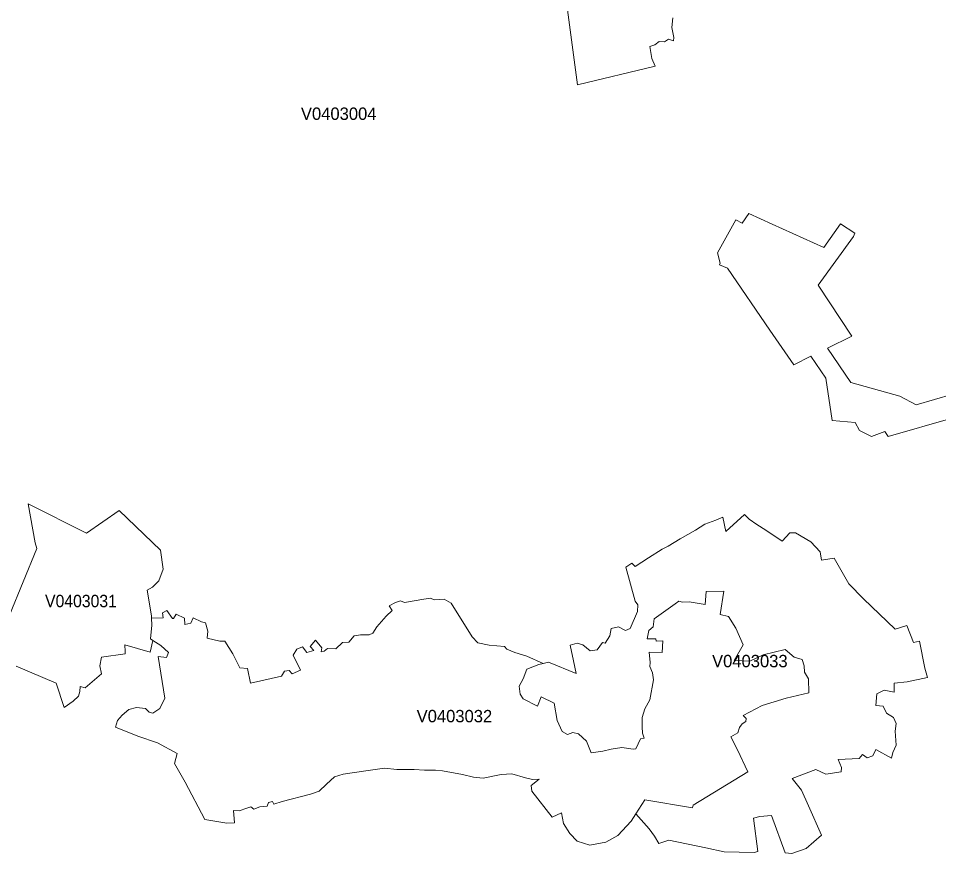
# Model space of a CAD drawing. Extents: x 369010 to 735936, y 6377141 to 6616555.
# Drawn here: x 413706 to 421131, y 6483708 to 6490450 of the extents above; entities that cross this region are included whole.
import ezdxf
from ezdxf.enums import TextEntityAlignment as Align

# ---------------------------------------------------------------- set-up
doc = ezdxf.new("R2010")
doc.units = 0
doc.header["$LTSCALE"] = 40
doc.layers.add('3', color=7, linetype='Continuous', lineweight=13)
doc.layers.add('4', color=7, linetype='Continuous')

msp = doc.modelspace()

# ---------------------------------------------------------------- linework, layer by layer
at = {"layer": '3'}
for points in [[(418988.28, 6490453.3), (418979.01, 6490376.01), (418996.05, 6490295.74), (418992.74, 6490269.76), (418951.04, 6490281.51), (418919.92, 6490261.32), (418877.55, 6490262.64), (418842.96, 6490235.83), (418800.76, 6490223.41), (418818.3, 6490126.1), (418844.62, 6490065.19), (418216.7, 6489912.43), (418137.42, 6490518.34)], [(418137.42, 6490518.34), (418216.7, 6489912.43), (418844.62, 6490065.19), (418818.3, 6490126.1), (418800.76, 6490223.41), (418842.96, 6490235.83), (418877.55, 6490262.64), (418919.92, 6490261.32), (418951.04, 6490281.51), (418992.74, 6490269.76), (418996.05, 6490295.74), (418979.01, 6490376.01), (418988.28, 6490453.3)], [(421250.22, 6487224.48), (420724.08, 6487074.87), (420696.61, 6487116.24), (420590.35, 6487074.7), (420493.54, 6487123.69), (420458.12, 6487186.58), (420273.58, 6487204.29), (420220.45, 6487545.39), (420100.3, 6487722.65), (419962.27, 6487652.48), (419770.94, 6487932.67), (419429.18, 6488432.99), (419362.65, 6488461.29), (419368.6, 6488473.04), (419347.75, 6488558.61), (419494.39, 6488822.59), (419547.18, 6488796.44), (419599.48, 6488874.06), (419787.83, 6488789.82), (420205.56, 6488600.15), (420339.62, 6488792.3), (420455.63, 6488716.5), (420445.87, 6488690.35), (420159.71, 6488296.45), (420430.81, 6487885.01), (420235.51, 6487788.69), (420423.53, 6487511.8), (420819.08, 6487401.08), (420950, 6487331.4), (421393.55, 6487459.33)], [(421393.55, 6487459.33), (420950, 6487331.4), (420819.08, 6487401.08), (420423.53, 6487511.8), (420235.51, 6487788.69), (420430.81, 6487885.01), (420159.71, 6488296.45), (420445.87, 6488690.35), (420455.63, 6488716.5), (420339.62, 6488792.3), (420205.56, 6488600.15), (419787.83, 6488789.82), (419599.48, 6488874.06), (419547.18, 6488796.44), (419494.39, 6488822.59), (419347.75, 6488558.61), (419368.6, 6488473.04), (419362.65, 6488461.29), (419429.18, 6488432.99), (419770.94, 6487932.67), (419962.27, 6487652.48), (420100.3, 6487722.65), (420220.45, 6487545.39), (420273.58, 6487204.29), (420458.12, 6487186.58), (420493.54, 6487123.69), (420590.35, 6487074.7), (420696.61, 6487116.24), (420724.08, 6487074.87), (421250.22, 6487224.48)], [(413522.51, 6485362.56), (413854.84, 6486170.06), (413841.93, 6486217.56), (413784.33, 6486530.36), (414256.35, 6486294.85), (414518.51, 6486477.56), (414851.83, 6486157.15), (414873.68, 6486004.88), (414840.42, 6485910.22), (414789.44, 6485857.42), (414744.09, 6485834.08), (414779.18, 6485628.03), (414779.84, 6485608.67), (414873.35, 6485610.65), (414868.88, 6485652.36), (414903.47, 6485670.57), (414948.65, 6485605.36), (414958.42, 6485605.36), (414980.6, 6485639.28), (415045.81, 6485607.01), (415049.12, 6485556.7), (415097.44, 6485568.45), (415116.31, 6485611.48)], [(413688.34, 6485220.56), (414009.92, 6485083.85), (414076.45, 6484886.08), (414147.95, 6484937.22), (414192.3, 6484977.6), (414202.23, 6485015.67), (414204.05, 6485056.21), (414246.09, 6485047.11), (414377.5, 6485159.16), (414363.93, 6485224.53), (414376.01, 6485292.72), (414568, 6485321.52), (414568.16, 6485338.4), (414564.85, 6485393.84), (414770.24, 6485333.1), (414790.27, 6485428.76), (414772.06, 6485440.35), (414781.83, 6485552.4), (414779.84, 6485608.67), (414779.18, 6485628.03), (414744.09, 6485834.08), (414789.44, 6485857.42), (414840.42, 6485910.22), (414873.68, 6486004.88), (414851.83, 6486157.15), (414518.51, 6486477.56), (414256.35, 6486294.85), (413784.33, 6486530.36), (413841.93, 6486217.56), (413854.84, 6486170.06), (413522.51, 6485362.56)], [(417939.81, 6485242.57), (417983.17, 6485253.16), (418207.59, 6485160.32), (418184.26, 6485262.93), (418159.43, 6485389.54), (418216.2, 6485407.74), (418259.73, 6485394.34), (418320.47, 6485345.52), (418376.57, 6485351.64), (418418.28, 6485412.38), (418441.78, 6485407.08), (418478.03, 6485465.01), (418489.78, 6485524.26), (418548.37, 6485538.66), (418605.8, 6485508.7), (418643.03, 6485525.58), (418701.46, 6485663.45), (418704.11, 6485716.24), (418683.25, 6485745.04), (418608.61, 6486019.61), (418656.28, 6486053.54), (418681.93, 6486025.07), (418789.34, 6486094.92), (418901.39, 6486165.09), (418948.39, 6486188.43), (419046.37, 6486248.84), (419169.34, 6486318.18), (419244.97, 6486367.67), (419333.19, 6486398.95), (419389.79, 6486423.77), (419413.29, 6486307.59), (419564.73, 6486444.46), (419602.46, 6486406.4), (419663.86, 6486363.86), (419738.01, 6486319.34), (419869.75, 6486230.3), (419930.66, 6486295.84), (419975.51, 6486297), (420099.97, 6486223.85), (420176.59, 6486143.41), (420185.53, 6486077.71), (420288.31, 6486091.61), (420406.48, 6485885.55), (420526.47, 6485763.41), (420780.68, 6485520.62), (420874.36, 6485548.75), (420928.81, 6485412.38), (420977.3, 6485421.48), (421019.84, 6485204.34), (421041.68, 6485128.21), (420877.17, 6485093.95), (420773.07, 6485083.19), (420773.73, 6485011.36), (420692.8, 6485026.92), (420633.05, 6484996.8), (420624.45, 6484903.45), (420684.03, 6484899.32), (420710.18, 6484840.56), (420766.45, 6484807.79), (420789.29, 6484758.8), (420781.51, 6484694.92), (420789.29, 6484583.53), (420762.64, 6484522.96), (420750.89, 6484479.1), (420624.78, 6484547.29), (420600.45, 6484496.31), (420556.1, 6484480.09), (420518.2, 6484508.73), (420490.72, 6484476.78), (420322.24, 6484467.02), (420347.06, 6484403.63), (420345.08, 6484369.04), (420221.61, 6484349.02), (420142, 6484385.59), (419950.19, 6484315.25), (420024.66, 6484220.58), (420082.59, 6484092.15), (420187.35, 6483855.81), (420063.72, 6483749.39), (419947.7, 6483707.85), (419892.92, 6483714.47), (419782.86, 6484016.19), (419689.19, 6484008.57), (419638.71, 6483994.84), (419671.64, 6483725.89), (419643.51, 6483716.13), (419401.21, 6483720.93), (419253.74, 6483753.2), (418953.85, 6483816.59), (418874.74, 6483789.12), (418839.32, 6483848.2), (418795.46, 6483909.11), (418688.71, 6484028.6), (418650.98, 6483970.51), (418544.39, 6483854.49), (418445.42, 6483801.36), (418316.83, 6483776.04), (418213.88, 6483807.49), (418155.63, 6483870.54), (418105.81, 6483949.82)], [(420347.06, 6484403.63), (420322.24, 6484467.02), (420490.72, 6484476.78), (420518.2, 6484508.73), (420556.1, 6484480.09), (420600.45, 6484496.31), (420624.78, 6484547.29), (420750.89, 6484479.1), (420762.64, 6484522.96), (420789.29, 6484583.53), (420781.51, 6484694.92), (420789.29, 6484758.8), (420766.45, 6484807.79), (420710.18, 6484840.56), (420684.03, 6484899.32), (420624.45, 6484903.45), (420633.05, 6484996.8), (420692.8, 6485026.92), (420773.73, 6485011.36), (420773.07, 6485083.19), (420877.17, 6485093.95), (421041.68, 6485128.21), (421019.84, 6485204.34), (420977.3, 6485421.48), (420928.81, 6485412.38), (420874.36, 6485548.75), (420780.68, 6485520.62), (420526.47, 6485763.41), (420406.48, 6485885.55), (420288.31, 6486091.61), (420185.53, 6486077.71), (420176.59, 6486143.41), (420099.97, 6486223.85), (419975.51, 6486297), (419930.66, 6486295.84), (419869.75, 6486230.3), (419738.01, 6486319.34), (419663.86, 6486363.86), (419602.46, 6486406.4), (419564.73, 6486444.46), (419413.29, 6486307.59), (419389.79, 6486423.77), (419333.19, 6486398.95), (419244.97, 6486367.67), (419169.34, 6486318.18), (419046.37, 6486248.84), (418948.39, 6486188.43), (418901.39, 6486165.09), (418789.34, 6486094.92), (418681.93, 6486025.07), (418656.28, 6486053.54), (418608.61, 6486019.61), (418683.25, 6485745.04), (418704.11, 6485716.24), (418701.46, 6485663.45), (418643.03, 6485525.58), (418605.8, 6485508.7), (418548.37, 6485538.66), (418489.78, 6485524.26), (418478.03, 6485465.01), (418441.78, 6485407.08), (418418.28, 6485412.38), (418376.57, 6485351.64), (418320.47, 6485345.52), (418259.73, 6485394.34), (418216.2, 6485407.74), (418159.43, 6485389.54), (418184.26, 6485262.93), (418207.59, 6485160.32), (417983.17, 6485253.16), (417939.81, 6485242.57)], [(415486.38, 6484052.76), (415549.93, 6484075.6), (415582.37, 6484085.2), (415605.87, 6484066.33), (415655.03, 6484086.53), (415712.29, 6484090.5), (415724.21, 6484121.28), (415756.98, 6484129.06), (415768.4, 6484107.38), (415835.92, 6484129.72), (416062.5, 6484186.82), (416132.01, 6484212.48), (416191.26, 6484267.75), (416257.13, 6484327.17), (416325.48, 6484350.01), (416509.36, 6484376.99), (416660.13, 6484397.67), (416761.09, 6484387.91), (416900.61, 6484387.25), (416982.2, 6484380.13), (417070.75, 6484380.46), (417128.34, 6484376.49), (417289.38, 6484346.53), (417377.92, 6484323.53), (417455.87, 6484317.74), (417602.68, 6484347.03), (417687.25, 6484350.67), (417798.47, 6484318.4), (417854.24, 6484306.48), (417907.54, 6484309.29), (417843.82, 6484258.82), (417848.45, 6484211.65), (418012.63, 6484002.95), (418089.92, 6484036.54), (418105.81, 6483949.82), (418155.63, 6483870.54), (418213.88, 6483807.49), (418316.83, 6483776.04), (418445.42, 6483801.36), (418544.39, 6483854.49), (418650.98, 6483970.51), (418688.71, 6484028.6), (418761.7, 6484140.98), (419145.17, 6484076.27), (419149.81, 6484099.93), (419592.37, 6484369.21), (419508.79, 6484545.14), (419455.33, 6484651.39), (419510.61, 6484684), (419523.68, 6484725.37), (419546.69, 6484754.83), (419576.15, 6484774.53), (419578.46, 6484798.69), (419555.62, 6484822.85), (419709.05, 6484902.46), (419902.19, 6484962.21), (420084.24, 6485004.91), (420080.77, 6485119.6), (420048.16, 6485172.56), (420045.35, 6485222.88), (420029.63, 6485275.18), (419965.25, 6485293.38), (419894.58, 6485355.61), (419716.99, 6485313.24), (419608.42, 6485262.1), (419481.64, 6485265.74), (419555.62, 6485394.01), (419494.88, 6485527.74), (419437.45, 6485621.74), (419367.61, 6485638.62), (419397.73, 6485826.3), (419256.23, 6485822.99), (419246.63, 6485717.4), (419118.36, 6485740.57), (419065.9, 6485737.93), (419035.94, 6485745.04), (419004.5, 6485723.53), (418836.18, 6485602.05), (418827.41, 6485538.16), (418794.14, 6485508.21), (418779.74, 6485441.67), (418849.09, 6485441.67), (418853.56, 6485423.96), (418905.86, 6485424.63), (418900.06, 6485332.44), (418795.13, 6485334.59), (418803.74, 6485251.34), (418801.75, 6485217.25), (418824.1, 6485166.77), (418830.22, 6485110.5), (418801.42, 6484948.97), (418760.21, 6484876.15), (418740.52, 6484805.31), (418739.19, 6484731.99), (418741.84, 6484680.85), (418754.75, 6484640.63), (418725.95, 6484633.35), (418687.22, 6484552.75), (418668.03, 6484551.43), (418574.35, 6484565.16)], [(417939.81, 6485242.57), (417905.22, 6485234.13), (417808.56, 6485196.89), (417778.44, 6485117.45), (417745.84, 6485059.36), (417756.26, 6484993.82), (417780.59, 6484955.92), (417895.12, 6484899.15), (417925.41, 6484972.47), (418028.35, 6484921.16), (418054.17, 6484781.64), (418092.9, 6484693.93), (418137.42, 6484669.6), (418179.79, 6484684.16), (418225.14, 6484673.73), (418291.34, 6484615.31), (418328.08, 6484522.3), (418423.08, 6484534.38), (418490.61, 6484552.09), (418574.35, 6484565.16), (418668.03, 6484551.43), (418687.22, 6484552.75), (418725.95, 6484633.35), (418754.75, 6484640.63), (418741.84, 6484680.85), (418739.19, 6484731.99), (418740.52, 6484805.31), (418760.21, 6484876.15), (418801.42, 6484948.97), (418830.22, 6485110.5), (418824.1, 6485166.77), (418801.75, 6485217.25), (418803.74, 6485251.34), (418795.13, 6485334.59), (418900.06, 6485332.44), (418905.86, 6485424.63), (418853.56, 6485423.96), (418849.09, 6485441.67), (418779.74, 6485441.67), (418794.14, 6485508.21), (418827.41, 6485538.16), (418836.18, 6485602.05), (419004.5, 6485723.53), (419035.94, 6485745.04), (419065.9, 6485737.93), (419118.36, 6485740.57), (419246.63, 6485717.4), (419256.23, 6485822.99), (419397.73, 6485826.3), (419367.61, 6485638.62), (419437.45, 6485621.74), (419494.88, 6485527.74), (419555.62, 6485394.01), (419481.64, 6485265.74), (419608.42, 6485262.1), (419716.99, 6485313.24), (419894.58, 6485355.61), (419965.25, 6485293.38), (420029.63, 6485275.18), (420045.35, 6485222.88), (420048.16, 6485172.56), (420080.77, 6485119.6), (420084.24, 6485004.91), (419902.19, 6484962.21), (419709.05, 6484902.46), (419555.62, 6484822.85), (419578.46, 6484798.69), (419576.15, 6484774.53), (419546.69, 6484754.83), (419523.68, 6484725.37), (419510.61, 6484684), (419455.33, 6484651.39), (419508.79, 6484545.14), (419592.37, 6484369.21), (419149.81, 6484099.93), (419145.17, 6484076.27), (418761.7, 6484140.98), (418688.71, 6484028.6), (418795.46, 6483909.11), (418839.32, 6483848.2), (418874.74, 6483789.12), (418953.85, 6483816.59), (419253.74, 6483753.2), (419401.21, 6483720.93), (419643.51, 6483716.13), (419671.64, 6483725.89), (419638.71, 6483994.84), (419689.19, 6484008.57), (419782.86, 6484016.19), (419892.92, 6483714.47), (419947.7, 6483707.85), (420063.72, 6483749.39), (420187.35, 6483855.81), (420082.59, 6484092.15), (420024.66, 6484220.58), (419950.19, 6484315.25), (420142, 6484385.59), (420221.61, 6484349.02), (420345.08, 6484369.04), (420347.06, 6484403.63)], [(418028.35, 6484921.16), (417925.41, 6484972.47), (417895.12, 6484899.15), (417780.59, 6484955.92), (417756.26, 6484993.82), (417745.84, 6485059.36), (417778.44, 6485117.45), (417808.56, 6485196.89), (417905.22, 6485234.13), (417939.81, 6485242.57), (417808.89, 6485301.49), (417713.23, 6485330.12), (417646.37, 6485359.25), (417627.5, 6485380.11), (417506.19, 6485390.37), (417413.51, 6485408.57), (417368.32, 6485457.56), (417198.18, 6485728.49), (417143.07, 6485761.59), (417060.15, 6485757.62), (417032.18, 6485769.37), (416977.9, 6485762.92), (416822.49, 6485733.79), (416788.23, 6485747.03), (416749.67, 6485733.95), (416696.71, 6485709.13), (416720.87, 6485669.41), (416673.37, 6485624.72), (416598.4, 6485539.32), (416565.13, 6485487.85), (416537.33, 6485473.95), (416466.16, 6485473.28), (416416.84, 6485465.34), (416373.81, 6485415.85), (416321.34, 6485412.38), (416267.89, 6485360.74), (416201.35, 6485362.73), (416173.88, 6485342.37), (416149.22, 6485337.9), (416154.35, 6485369.84), (416104.2, 6485431.08), (416060.34, 6485378.29), (416089.8, 6485348.33), (416033.7, 6485331.28), (415997.45, 6485376.46), (415951.77, 6485358.26), (415923.64, 6485309.93), (415981.73, 6485189.28), (415914.54, 6485158.5), (415891.7, 6485185.31), (415852.47, 6485179.51), (415827.98, 6485141.45), (415577.9, 6485084.68), (415554.4, 6485201.53), (415492.5, 6485207.49), (415437.55, 6485320.52), (415373.01, 6485422.64), (415332.46, 6485422.64), (415228.69, 6485447.96), (415234.65, 6485502.74), (415216.94, 6485571.92), (415184.99, 6485577.72), (415116.31, 6485611.48), (415097.44, 6485568.45), (415049.12, 6485556.7), (415045.81, 6485607.01), (414980.6, 6485639.28), (414958.42, 6485605.36), (414948.65, 6485605.36), (414903.47, 6485670.57), (414868.88, 6485652.36), (414873.35, 6485610.65), (414779.84, 6485608.67), (414781.83, 6485552.4), (414772.06, 6485440.35), (414790.27, 6485428.76), (414855.14, 6485387.39), (414918.37, 6485330.62), (414900, 6485289.74), (414834.29, 6485298.18), (414886.92, 6484962.21), (414847.53, 6484879.62), (414790.6, 6484840.89), (414760.15, 6484848.51), (414730.69, 6484879.95), (414658.86, 6484888.39), (414597.29, 6484871.51), (414542.84, 6484826.16), (414505.1, 6484781.64), (414490.54, 6484727.85), (414669.61, 6484657.02), (414828.33, 6484602.9), (414988.21, 6484515.18), (414965.7, 6484436.4), (415052.09, 6484284.8), (415211.64, 6483983.42), (415387.9, 6483952.8), (415448.81, 6483957.27), (415441.86, 6484056.57), (415486.38, 6484052.76)], [(415116.31, 6485611.48), (415184.99, 6485577.72), (415216.94, 6485571.92), (415234.65, 6485502.74), (415228.69, 6485447.96), (415332.46, 6485422.64), (415373.01, 6485422.64), (415437.55, 6485320.52), (415492.5, 6485207.49), (415554.4, 6485201.53), (415577.9, 6485084.68), (415827.98, 6485141.45), (415852.47, 6485179.51), (415891.7, 6485185.31), (415914.54, 6485158.5), (415981.73, 6485189.28), (415923.64, 6485309.93), (415951.77, 6485358.26), (415997.45, 6485376.46), (416033.7, 6485331.28), (416089.8, 6485348.33), (416060.34, 6485378.29), (416104.2, 6485431.08), (416154.35, 6485369.84), (416149.22, 6485337.9), (416173.88, 6485342.37), (416201.35, 6485362.73), (416267.89, 6485360.74), (416321.34, 6485412.38), (416373.81, 6485415.85), (416416.84, 6485465.34), (416466.16, 6485473.28), (416537.33, 6485473.95), (416565.13, 6485487.85), (416598.4, 6485539.32), (416673.37, 6485624.72), (416720.87, 6485669.41), (416696.71, 6485709.13), (416749.67, 6485733.95), (416788.23, 6485747.03), (416822.49, 6485733.79), (416977.9, 6485762.92), (417032.18, 6485769.37), (417060.15, 6485757.62), (417143.07, 6485761.59), (417198.18, 6485728.49), (417368.32, 6485457.56), (417413.51, 6485408.57), (417506.19, 6485390.37), (417627.5, 6485380.11), (417646.37, 6485359.25), (417713.23, 6485330.12), (417808.89, 6485301.49), (417939.81, 6485242.57)], [(418105.81, 6483949.82), (418089.92, 6484036.54), (418012.63, 6484002.95), (417848.45, 6484211.65), (417843.82, 6484258.82), (417907.54, 6484309.29), (417854.24, 6484306.48), (417798.47, 6484318.4), (417687.25, 6484350.67), (417602.68, 6484347.03), (417455.87, 6484317.74), (417377.92, 6484323.53), (417289.38, 6484346.53), (417128.34, 6484376.49), (417070.75, 6484380.46), (416982.2, 6484380.13), (416900.61, 6484387.25), (416761.09, 6484387.91), (416660.13, 6484397.67), (416509.36, 6484376.99), (416325.48, 6484350.01), (416257.13, 6484327.17), (416191.26, 6484267.75), (416132.01, 6484212.48), (416062.5, 6484186.82), (415835.92, 6484129.72), (415768.4, 6484107.38), (415756.98, 6484129.06), (415724.21, 6484121.28), (415712.29, 6484090.5), (415655.03, 6484086.53), (415605.87, 6484066.33), (415582.37, 6484085.2), (415549.93, 6484075.6), (415486.38, 6484052.76), (415441.86, 6484056.57), (415448.81, 6483957.27), (415387.9, 6483952.8), (415211.64, 6483983.42), (415052.09, 6484284.8), (414965.7, 6484436.4), (414988.21, 6484515.18), (414828.33, 6484602.9), (414669.61, 6484657.02), (414490.54, 6484727.85), (414505.1, 6484781.64), (414542.84, 6484826.16), (414597.29, 6484871.51), (414658.86, 6484888.39), (414730.69, 6484879.95), (414760.15, 6484848.51), (414790.6, 6484840.89), (414847.53, 6484879.62), (414886.92, 6484962.21), (414834.29, 6485298.18), (414900, 6485289.74), (414918.37, 6485330.62), (414855.14, 6485387.39), (414790.27, 6485428.76), (414770.24, 6485333.1), (414564.85, 6485393.84), (414568.16, 6485338.4), (414568, 6485321.52), (414376.01, 6485292.72), (414363.93, 6485224.53), (414377.5, 6485159.16), (414246.09, 6485047.11), (414204.05, 6485056.21), (414202.23, 6485015.67), (414192.3, 6484977.6), (414147.95, 6484937.22), (414076.45, 6484886.08), (414009.92, 6485083.85), (413688.34, 6485220.56)], [(418574.35, 6484565.16), (418490.61, 6484552.09), (418423.08, 6484534.38), (418328.08, 6484522.3), (418291.34, 6484615.31), (418225.14, 6484673.73), (418179.79, 6484684.16), (418137.42, 6484669.6), (418092.9, 6484693.93), (418054.17, 6484781.64), (418028.35, 6484921.16)]]:
    msp.add_lwpolyline(points, dxfattribs=at)

# ---------------------------------------------------------------- texts
at = {"layer": '4'}
for s, p in [('V0403004', (416290.85, 6489630.47)), ('V0403033', (419608.42, 6485212.1)), ('V0403032', (417224.6, 6484767.66))]:
    msp.add_text(s, height=100, dxfattribs=at).set_placement(p, align=Align.CENTER)
at = {"layer": '4', "width": 0.95}
msp.add_text('V0403031', height=100, dxfattribs=at).set_placement((414211.03, 6485696.77), align=Align.CENTER)

doc.saveas('drawing.dxf')
